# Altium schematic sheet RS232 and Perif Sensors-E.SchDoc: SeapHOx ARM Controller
size Letter; DocumentNumber: 1; Revision: E; SheetNumber: 6; SheetTotal: 7
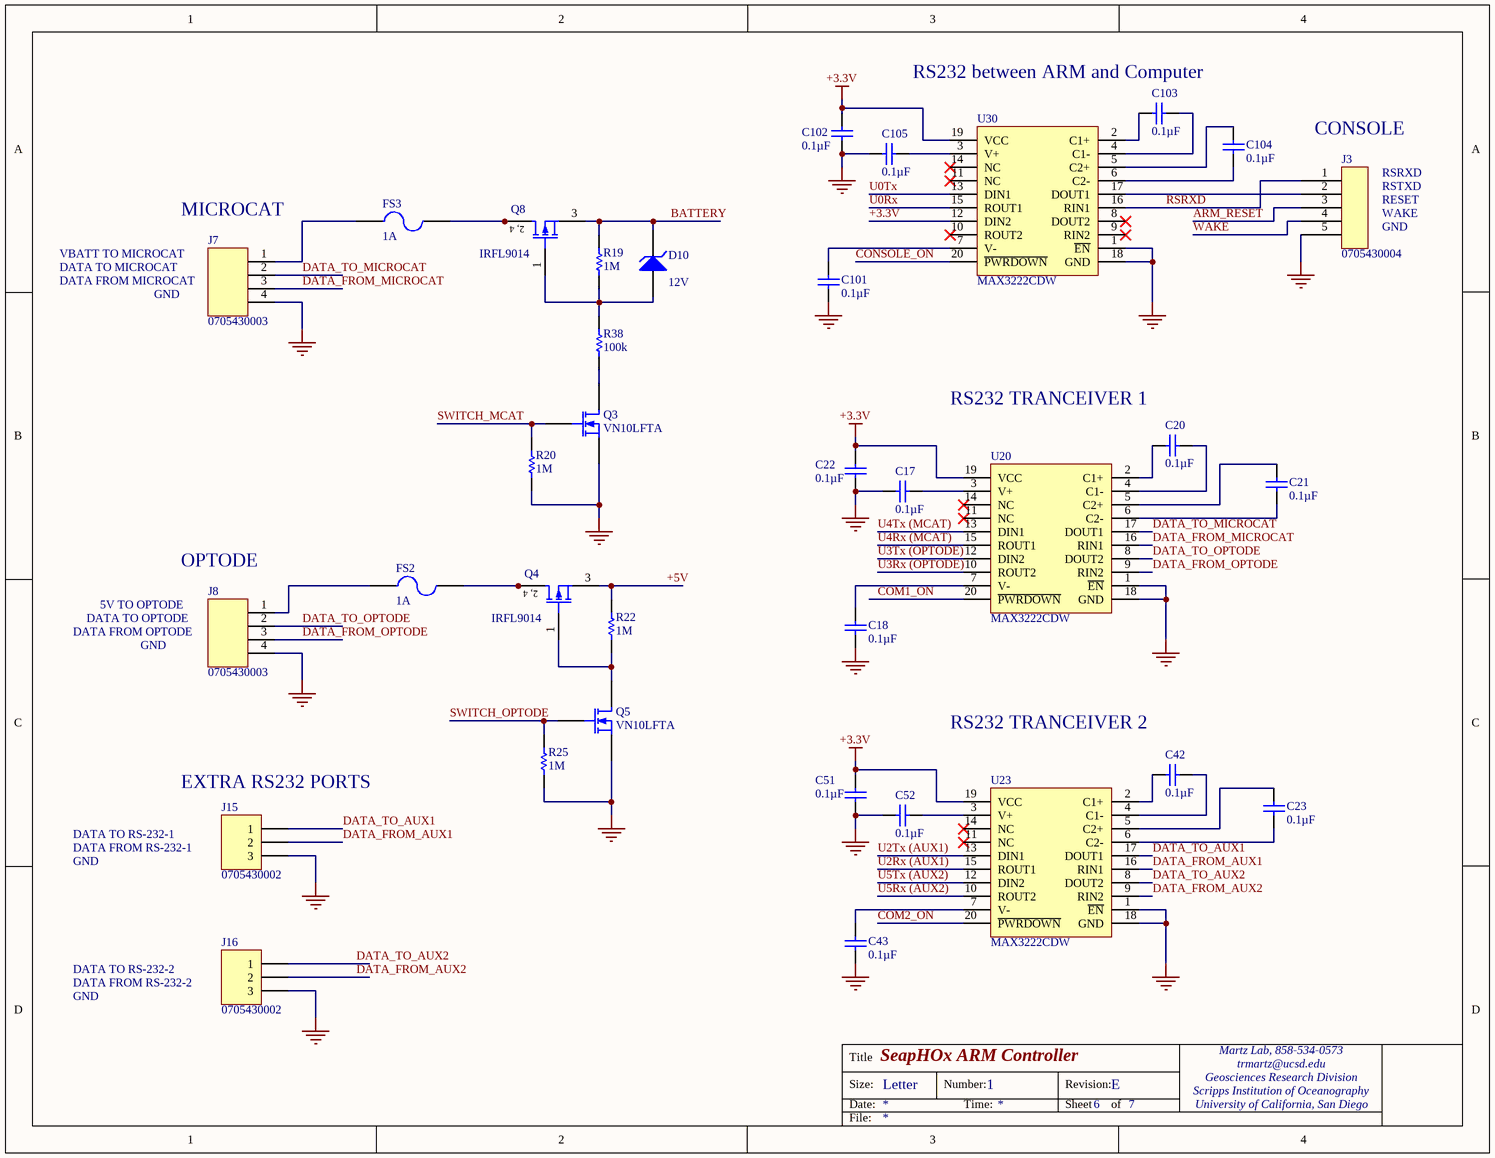
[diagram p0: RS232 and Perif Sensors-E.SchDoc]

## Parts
C17  Capacitance: 0.1µF  [CAPC0603(1608)100_M]  (hidden comment: 0.1uF/50V)
C18  Capacitance: 0.1µF  [CAPC0603(1608)100_M]  (hidden comment: 0.1uF/50V)
C20  Capacitance: 0.1µF  [CAPC0603(1608)100_M]  (hidden comment: 0.1uF/50V)
C21  Capacitance: 0.1µF  [CAPC0603(1608)100_M]  (hidden comment: 0.1uF/50V)
C22  Capacitance: 0.1µF  [CAPC0603(1608)100_M]  (hidden comment: 0.1uF/50V)
C23  Capacitance: 0.1µF  [CAPC0603(1608)100_M]  (hidden comment: 0.1uF/50V)
C42  Capacitance: 0.1µF  [CAPC0603(1608)100_M]  (hidden comment: 0.1uF/50V)
C43  Capacitance: 0.1µF  [CAPC0603(1608)100_M]  (hidden comment: 0.1uF/50V)
C51  Capacitance: 0.1µF  [CAPC0603(1608)100_M]  (hidden comment: 0.1uF/50V)
C52  Capacitance: 0.1µF  [CAPC0603(1608)100_M]  (hidden comment: 0.1uF/50V)
C101  Capacitance: 0.1µF  [CAPC0603(1608)100_M]  (hidden comment: 0.1uF/50V)
C102  Capacitance: 0.1µF  [CAPC0603(1608)100_M]  (hidden comment: 0.1uF/50V)
C103  Capacitance: 0.1µF  [CAPC0603(1608)100_M]  (hidden comment: 0.1uF/50V)
C104  Capacitance: 0.1µF  [CAPC0603(1608)100_M]  (hidden comment: 0.1uF/50V)
C105  Capacitance: 0.1µF  [CAPC0603(1608)100_M]  (hidden comment: 0.1uF/50V)
D10  Voltage - Zener (Nom) (Vz): 12V  [SOD323F 1005]
FS2  Current Rating: 1A  [FUSE-NANO-SMD]  (hidden comment: 5A)
FS3  Current Rating: 1A  [FUSE-NANO-SMD]  (hidden comment: 5A)
J3  0705430004  [70543-0004]
J7  0705430003  [70543-0003]
J8  0705430003  [70543-0003]
J15  0705430002  [70543-0002]
J16  0705430002  [70543-0002]
Q3  VN10LFTA  [SOT23-3]
Q4  IRFL9014  [SOT-223]
Q5  VN10LFTA  [SOT23-3]
Q8  IRFL9014  [SOT-223]
R19  Resistance (Ohms): 1M  [RESC0805(2012)_N]  (hidden comment: ERJ-6GEYJ105V)
R20  Resistance (Ohms): 1M  [RESC0805(2012)_N]  (hidden comment: ERJ-6GEYJ105V)
R22  Resistance (Ohms): 1M  [RESC0805(2012)_N]  (hidden comment: ERJ-6GEYJ105V)
R25  Resistance (Ohms): 1M  [RESC0805(2012)_N]  (hidden comment: ERJ-6GEYJ105V)
R38  Resistance (Ohms): 100k  [RESC0805(2012)_N]  (hidden comment: ERJ-6GEYJ104V)
U20  MAX3222CDW  [SOIC20]
U23  MAX3222CDW  [SOIC20]
U30  MAX3222CDW  [SOIC20]

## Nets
+3.3V: C22.1 C51.1 C102.1 U20.19(VCC) U23.19(VCC) U30.12(DIN2) U30.19(VCC)
GND: C17.2 C18.2 C22.2 C43.2 C51.2 C52.2 C101.2 C102.2 C105.2 J3.5 J7.4 J8.4 J15.3 J16.3 Q3.2(S) Q5.2(S) R20.1 R25.1 U20.1(~{EN}) U20.18(GND) U23.1(~{EN}) U23.18(GND) U30.1(~{EN}) U30.18(GND)
+5V: Q4.3(S) R22.2
ARM_RESET: J3.3
BATTERY: D10.2(K) Q8.3(S) R19.2
COM1_ON: U20.20(~{PWRDOWN})
COM2_ON: U23.20(~{PWRDOWN})
CONSOLE_ON: U30.20(~{PWRDOWN})
DATA_FROM_AUX1: J15.2 U23.16(RIN1)
DATA_FROM_AUX2: J16.2 U23.9(RIN2)
DATA_FROM_MICROCAT: J7.3 U20.16(RIN1)
DATA_FROM_OPTODE: J8.3 U20.9(RIN2)
DATA_TO_AUX1: J15.1 U23.17(DOUT1)
DATA_TO_AUX2: J16.1 U23.8(DOUT2)
DATA_TO_MICROCAT: J7.2 U20.17(DOUT1)
DATA_TO_OPTODE: J8.2 U20.8(DOUT2)
RSRXD: J3.1 U30.16(RIN1)
SWITCH_MCAT: Q3.1(G) R20.2
SWITCH_OPTODE: Q5.1(G) R25.2
U0Rx: U30.15(ROUT1)
U0Tx: U30.13(DIN1)
U2Rx (AUX1): U23.15(ROUT1)
U2Tx (AUX1): U23.13(DIN1)
U3Rx (OPTODE): U20.10(ROUT2)
U3Tx (OPTODE): U20.12(DIN2)
U4Rx (MCAT): U20.15(ROUT1)
U4Tx (MCAT): U20.13(DIN1)
U5Rx (AUX2): U23.10(ROUT2)
U5Tx (AUX2): U23.12(DIN2)
WAKE: J3.4
NetC17_1: C17.1 U20.3(V+)
NetC18_1: C18.1 U20.7(V-)
NetC20_1: C20.1 U20.2(C1+)
NetC20_2: C20.2 U20.4(C1-)
NetC21_1: C21.1 U20.5(C2+)
NetC21_2: C21.2 U20.6(C2-)
NetC23_1: C23.1 U23.5(C2+)
NetC23_2: C23.2 U23.6(C2-)
NetC42_1: C42.1 U23.2(C1+)
NetC42_2: C42.2 U23.4(C1-)
NetC43_1: C43.1 U23.7(V-)
NetC52_1: C52.1 U23.3(V+)
NetC101_1: C101.1 U30.7(V-)
NetC103_1: C103.1 U30.2(C1+)
NetC103_2: C103.2 U30.4(C1-)
NetC104_1: C104.1 U30.5(C2+)
NetC104_2: C104.2 U30.6(C2-)
NetC105_1: C105.1 U30.3(V+)
NetD10_1: D10.1(A) Q8.1(G) R19.1 R38.2
NetFS2_1: FS2.1 J8.1
NetFS2_2: FS2.2 Q4.2(D) Q4.4(D)
NetFS3_1: FS3.1 J7.1
NetFS3_2: FS3.2 Q8.2(D) Q8.4(D)
NetJ3_2: J3.2 U30.17(DOUT1)
NetQ3_3: Q3.3(D) R38.1
NetQ4_1: Q4.1(G) Q5.3(D) R22.1

Not connected (* = marked no-connect by the designer): U20 11(NC)* 14(NC)*; U23 11(NC)* 14(NC)*; U30 8(DOUT2)* 9(RIN2)* 10(ROUT2)* 11(NC)* 14(NC)*

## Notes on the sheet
- (near C103) RS232 between ARM and Computer
- (near J3) CONSOLE
- (near J7) MICROCAT
- (near J3) RSRXD
- (near J3) RSTXD
- (near J3) RESET
- (near J3) WAKE
- (near J3) GND
- DATA TO MICROCAT
- DATA FROM MICROCAT
- VBATT TO MICROCAT
- GND
- RS232 TRANCEIVER 1
- (near J8) OPTODE
- DATA FROM OPTODE
- DATA TO OPTODE
- 5V TO OPTODE
- RS232 TRANCEIVER 2
- DATA TO RS-232-1
- (near J15) EXTRA RS232 PORTS
- DATA FROM RS-232-1
- DATA TO RS-232-2
- DATA FROM RS-232-2

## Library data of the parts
C17 C18 C20-C23 C42 C43 C51 C52 C101-C105 = C0603C104K5RACTU: CAP CER 0.1UF 50V 10% X7R 0603; Manufacturer: Kemet
D10 = CZRF52C12: DIODE ZENER 12V 200MW 1005; Manufacturer: Comchip Technology; Voltage - Forward (Vf) (Max) @ If: 900mV @ 10mA; Current - Reverse Leakage @ Vr: 100nA @ 9V; Tolerance: ±5%; Impedance (Max) (Zzt): 20 Ohm
FS2 FS3 = 0157001.DR: FUSE FAST 125VAC, 125VDC 1A SMD; Manufacturer: Littelfuse Inc; Fuse Type: Board Mount (Cartridge Style Excluded); Voltage Rating - AC: 125V; Breaking Capacity @ Rated Voltage: 50A; Melting I²t: 0.459; Approvals: cULus, PSE; DC Cold Resistance: 0.1537 Ohm
J3 = 0705430004: CONN HEADER 5POS .100 VERT GOLD; Manufacturer: Molex Inc; Connector Type: Header, Shrouded; Number of Positions: 5; Number of Positions Loaded: All; Pitch: 0.100" (2.54mm)
J7 J8 = 0705430003: CONN HEADER 4POS .100 VERT GOLD; Manufacturer: Molex Inc; Connector Type: Header, Shrouded; Number of Positions: 4; Number of Positions Loaded: All; Pitch: 0.100" (2.54mm)
J15 J16 = 0705430002: CONN HEADER 3POS .100 VERT GOLD; Manufacturer: Molex Inc; Connector Type: Header, Shrouded; Number of Positions: 3; Number of Positions Loaded: All; Pitch: 0.100" (2.54mm)
Q3 Q5 = VN10LFTA: MOSFET N-CH 60V 150MA SOT23-3; Manufacturer: Diodes Inc; FET Type: MOSFET N-Channel, Metal Oxide; FET Feature: Standard; Current - Continuous Drain (Id) @ 25° C: 150mA (Ta); Rds On (Max) @ Id, Vgs: 5 Ohm @ 500mA, 10V; Vgs(th) (Max) @ Id: 2.5V @ 1mA; Input Capacitance (Ciss) @ Vds: 60pF @ 25V; Power - Max: 330mW
Q4 Q8 = IRFL9014TRPBF: MOSFET P-CH 60V 1.8A SOT223; Manufacturer: Vishay Siliconix; FET Type: MOSFET P-Channel, Metal Oxide; FET Feature: Standard; Current - Continuous Drain (Id) @ 25° C: 1.8A (Tc); Rds On (Max) @ Id, Vgs: 500 mOhm @ 1.1A, 10V; Vgs(th) (Max) @ Id: 4V @ 250µA; Gate Charge (Qg) @ Vgs: 12nC @ 10V; Input Capacitance (Ciss) @ Vds: 270pF @ 25V; Power - Max: 2W
R19 R20 R22 R25 = ERJ-6GEYJ105V: RES 1M OHM 1/8W 5% 0805 SMD; Manufacturer: Panasonic Electronic Components; Power (Watts): 0.125W, 1/8W; Temperature Coefficient: ±200ppm/°C
R38 = ERJ-6GEYJ104V: RES 100K OHM 1/8W 5% 0805 SMD; Manufacturer: Panasonic Electronic Components; Power (Watts): 0.125W, 1/8W; Temperature Coefficient: ±200ppm/°C
U20 U23 U30 = MAX3222CDW: IC DRVR/RCVR MULTCH RS232 20SOIC; Manufacturer: Texas Instruments; Number of Drivers/Receivers: 2/2; Duplex: Full; Receiver Hysteresis: 300mV; Data Rate: 250kbps; Voltage - Supply: 3 V ~ 5.5 V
